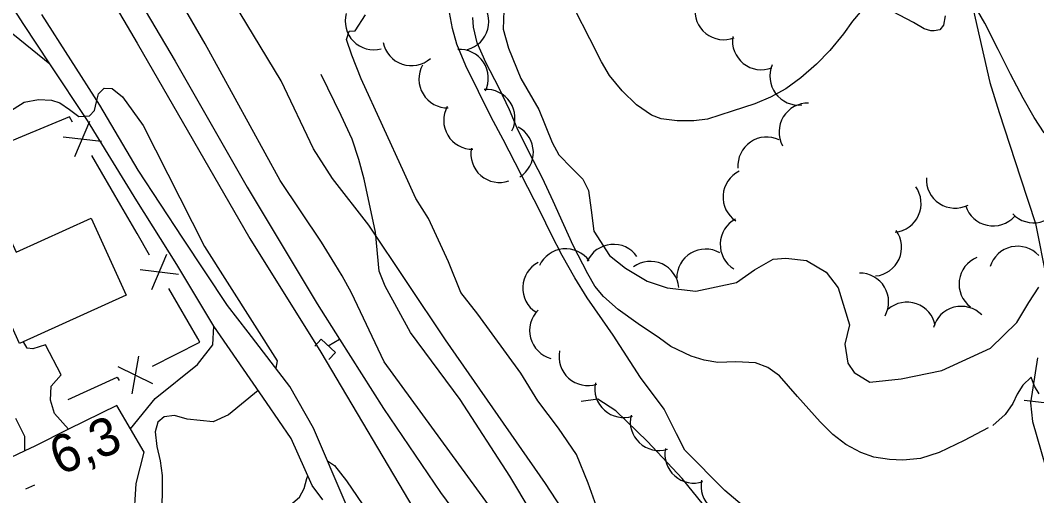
# Model space of a CAD drawing. Extents: x 362852 to 366875, y 5563573 to 5566479.
# Drawn here: x 364339.6 to 364445.4, y 5564921.9 to 5564971.4 of the extents above; entities that cross this region are included whole.
import ezdxf

# ---------------------------------------------------------------- set-up
doc = ezdxf.new("R2010")
doc.units = 0
for name, color, linetype in [('Niveau 1', 7, 'Continuous'), ('Niveau 19', 7, 'Continuous'), ('Niveau 2', 7, 'Continuous'), ('Niveau 21', 7, 'Continuous'), ('Niveau 22', 7, 'Continuous'), ('Niveau 26', 7, 'Continuous'), ('Niveau 3', 7, 'Continuous'), ('Niveau 31', 7, 'Continuous'), ('Niveau 37', 7, 'Continuous'), ('Niveau 4', 7, 'Continuous'), ('Niveau 44', 7, 'Continuous')]:
    doc.layers.add(name, color=color, linetype=linetype)

msp = doc.modelspace()

# ---------------------------------------------------------------- linework, layer by layer
at = {"layer": 'Niveau 1'}
for points in [[(364401.32, 5564938.56), (364400.2, 5564940.18), (364398.62, 5564942.47), (364397.33, 5564944.56), (364396.02, 5564946.86), (364394.86, 5564949.08), (364393.75, 5564951.38), (364392.42, 5564953.96), (364391.12, 5564956.53), (364389.85, 5564958.94), (364388.61, 5564961.29), (364387.3, 5564963.94), (364385.98, 5564966.61), (364385.03, 5564968.88), (364384.58, 5564970.52), (364384.29, 5564972.19), (364384.07, 5564973.39), (364383.72, 5564973.8)], [(364470.03, 5564888.41), (364466.89, 5564889.74), (364464.83, 5564893.08), (364460.41, 5564900.33), (364455.85, 5564906.41), (364452.83, 5564911.75), (364450.44, 5564916.21), (364449.3, 5564917.79), (364448.42, 5564918.36), (364447.47, 5564916.05), (364444.95, 5564913.74), (364439.93, 5564911.44), (364435.17, 5564911.23), (364430.09, 5564912.75), (364425.67, 5564914.79), (364420.35, 5564916.68), (364416.81, 5564919.14), (364412.95, 5564922.4), (364408.78, 5564926.59), (364407.91, 5564928.29), (364406.62, 5564930.86), (364404.17, 5564934.15), (364401.32, 5564938.56)]]:
    msp.add_lwpolyline(points, dxfattribs=at)
at = {"layer": 'Niveau 19'}
for points in [[(364371.09, 5564921.42), (364369.98, 5564922.91), (364367.8, 5564927.81), (364365.23, 5564931.56), (364359.73, 5564939.51), (364355.89, 5564945.92), (364351.73, 5564952.56), (364346.58, 5564960.94), (364342.66, 5564966.84), (364339.96, 5564970.91), (364335.29, 5564978.17)], [(364446.52, 5564826.2), (364439.4, 5564834), (364433.05, 5564842.48), (364429.25, 5564847.71), (364423.9, 5564854.18), (364418.74, 5564859.91), (364412.38, 5564866.59), (364407.73, 5564872.41), (364402.82, 5564877.5), (364399.08, 5564882.94), (364390.62, 5564894.66), (364384.3, 5564903.22), (364378.76, 5564910.47), (364376.94, 5564913.47), (364374.94, 5564917.45), (364373.52, 5564920.93), (364370.11, 5564928.88), (364367.65, 5564933.24), (364363.33, 5564938.88), (364361.15, 5564941.66), (364356.52, 5564948.67), (364351.86, 5564955.74), (364347.86, 5564962.52), (364341.84, 5564971.98)], [(364344.62, 5564928.77), (364343.16, 5564930.41), (364342.73, 5564931.79), (364342.82, 5564933.26), (364343.84, 5564934.43), (364342.21, 5564937.56), (364340.89, 5564937.14), (364340.3, 5564937.21), (364339.94, 5564937.89)], [(364340.06, 5564926.52), (364340.07, 5564928.02), (364339.12, 5564929.88)]]:
    msp.add_lwpolyline(points, dxfattribs=at)
at = {"layer": 'Niveau 2'}
for points in [[(364213.35, 5565146.39), (364232.53, 5565126.45), (364248.39, 5565109.34), (364263.13, 5565093.41), (364276.11, 5565079.71), (364286.64, 5565068.01), (364298.72, 5565050.81), (364312.47, 5565031.31), (364325.73, 5565011.49), (364339.55, 5564989.79), (364351.77, 5564968.99), (364363.49, 5564948.63), (364370.89, 5564936.8), (364381.12, 5564919.52), (364394.15, 5564902.4), (364400.15, 5564894.19), (364412.12, 5564878.44), (364425.03, 5564863.91), (364445.83, 5564836.95)], [(364448.42, 5564846.74), (364439.7, 5564857.82), (364433.96, 5564865.25), (364422.86, 5564878.54), (364417.41, 5564885.85), (364417.07, 5564886.4), (364416.7, 5564888.08), (364410.82, 5564892.76), (364404.29, 5564900.44), (364392.1, 5564915.78), (364377.46, 5564935.81), (364374.07, 5564942.97), (364373.1, 5564944.76), (364372.34, 5564946.01), (364370.94, 5564948.25), (364366.66, 5564954.67), (364358.85, 5564968.9), (364349.12, 5564985.71)], [(364400.99, 5564912.83), (364394.28, 5564923.11), (364383.87, 5564938.1), (364375.87, 5564950.03), (364372.1, 5564954.9), (364370.12, 5564957.96), (364366.75, 5564965.06), (364358.11, 5564979.35)], [(364446.2, 5564959.65), (364445.14, 5564961.23), (364444.02, 5564963.25), (364442.7, 5564965.76), (364441.39, 5564968.33), (364440.02, 5564971.08), (364438.73, 5564973.29)], [(364373.83, 5564970.24), (364374.45, 5564970.25), (364375.52, 5564971.93)], [(364389.95, 5564972.4), (364389.87, 5564970.45), (364390.43, 5564968.45), (364391.7, 5564965.31), (364393.57, 5564962.06), (364394.95, 5564958.65), (364395.66, 5564957.34), (364397.02, 5564955.97), (364398.16, 5564954.83), (364398.76, 5564953.65), (364399.03, 5564951.6), (364399.3, 5564949.41), (364400.94, 5564946.87), (364402.59, 5564945.56), (364404.87, 5564944.2), (364406.94, 5564943.5), (364409.92, 5564943.17), (364414.15, 5564944.04), (364416.02, 5564945.36), (364417.99, 5564946.48), (364419.31, 5564946.58), (364421.44, 5564946.34), (364423.48, 5564945.13), (364424.76, 5564943.49), (364425.94, 5564939.64), (364425.45, 5564937.64), (364425.75, 5564935.66), (364426.4, 5564934.69), (364428.04, 5564933.69), (364431.3, 5564934.03), (364435.53, 5564934.9), (364440.59, 5564937.22), (364443.34, 5564939.89), (364444.61, 5564941.96), (364445.64, 5564943.56)], [(364427.05, 5564972.21), (364426.23, 5564971.27), (364425.29, 5564969.95), (364423.87, 5564968.23), (364422.47, 5564966.8), (364420.84, 5564965.38), (364419.29, 5564964.22), (364417.69, 5564963.35), (364416.05, 5564962.68), (364413.72, 5564961.89), (364411.15, 5564961.06), (364409.73, 5564960.91), (364407.97, 5564960.91), (364406.33, 5564961.11), (364405.3, 5564961.5), (364403.76, 5564962.57), (364402.24, 5564964.03), (364400.94, 5564965.63), (364400.12, 5564967.04), (364398.89, 5564969.42), (364397.31, 5564972.5)], [(364435.89, 5564971.82), (364435.72, 5564970.85), (364435.33, 5564970.38), (364434.75, 5564970.26), (364434.39, 5564970.27), (364433.68, 5564970.46), (364432.57, 5564971.13), (364430.39, 5564972.28)], [(364440.35, 5564928.91), (364437.86, 5564927.61), (364435.25, 5564926.34), (364433.32, 5564925.73), (364431.47, 5564925.54), (364430.09, 5564925.61), (364428.46, 5564925.86), (364427.12, 5564926.35), (364425.55, 5564927.19), (364424.2, 5564928.23), (364422.86, 5564929.55), (364420.5, 5564932.2), (364418.62, 5564934.33), (364417.43, 5564935.19), (364416.14, 5564935.68), (364414.1, 5564935.79), (364412.23, 5564935.71), (364410.8, 5564935.96), (364409.43, 5564936.4), (364407.31, 5564937.4), (364406.15, 5564938.25), (364403.91, 5564939.74), (364401.83, 5564941.25), (364400.31, 5564942.61), (364399.4, 5564943.68), (364398.68, 5564944.95), (364397.16, 5564947.9), (364396.19, 5564950.06), (364395.07, 5564952.51), (364393.96, 5564954.93), (364392.57, 5564957.61), (364391.32, 5564960.12), (364390.51, 5564962.05), (364389.44, 5564964.31), (364388.05, 5564966.98), (364387.16, 5564969.01), (364386.76, 5564970.66), (364386.71, 5564971.67)], [(364436.08, 5564904.15), (364425.61, 5564904.22), (364421.12, 5564905.49), (364410.33, 5564908.53), (364404.44, 5564913.58), (364401.28, 5564917.39), (364399.75, 5564920.25), (364398.7, 5564923.17), (364397.49, 5564926.16), (364395.64, 5564928.89), (364393.49, 5564931.74), (364391.71, 5564934.62), (364387.24, 5564940.76), (364385.46, 5564943.01), (364384.17, 5564946.22), (364382.1, 5564950.72), (364380.76, 5564952.79), (364379.58, 5564955.41), (364375.09, 5564965.28), (364374.1, 5564967.74), (364373.56, 5564969.38), (364373.83, 5564970.24)], [(364336.47, 5564960.63), (364340.01, 5564962.83), (364341.5, 5564963.13), (364342.84, 5564963.06), (364343.7, 5564962.78), (364344.73, 5564962.08), (364345.7, 5564961.36), (364346.8, 5564961.43), (364347.33, 5564961.96), (364347.53, 5564962.86), (364347.75, 5564963.69), (364348.31, 5564964.3), (364349.14, 5564964.26), (364350.23, 5564963.4), (364352.38, 5564960.41), (364358.77, 5564947.82), (364366.33, 5564935.9), (364366.19, 5564935.14)], [(364445.67, 5564932.47), (364445.2, 5564933.25), (364444.85, 5564934.2), (364443.98, 5564933.35), (364443.39, 5564932.42), (364442.93, 5564931.44), (364442.12, 5564930.32), (364440.86, 5564929.17), (364440.86, 5564929.17)], [(364364.36, 5564932.81), (364361.26, 5564930.27), (364359.68, 5564929.56), (364356.96, 5564929.82), (364355.63, 5564930.21), (364354.56, 5564930.08), (364353.92, 5564929.51), (364353.63, 5564928.52)], [(364353.63, 5564928.52), (364353.82, 5564926.97), (364354.17, 5564925.5), (364354.36, 5564923.95), (364354.37, 5564922.09), (364354.29, 5564920.12), (364354.69, 5564919.29), (364355.25, 5564918.83), (364356.02, 5564918.78), (364361.41, 5564920.05), (364362.87, 5564920.15), (364364.59, 5564919.73), (364366.04, 5564919.7), (364366.76, 5564920.06), (364368.65, 5564921.71), (364369.16, 5564922.6), (364369.42, 5564923.64), (364369.53, 5564923.91)], [(364371.57, 5564925.48), (364372.29, 5564925.01), (364373.56, 5564923.41), (364380.2, 5564913.6)]]:
    msp.add_lwpolyline(points, dxfattribs=at)
at = {"layer": 'Niveau 21'}
msp.add_lwpolyline([(364351.41, 5564919.16), (364351.67, 5564923.13), (364352.48, 5564926.38), (364351.06, 5564928.82), (364349.63, 5564931.26), (364344.62, 5564928.77), (364341.09, 5564927.01), (364340.06, 5564926.52), (364332.68, 5564923.01)], dxfattribs=at)
at = {"layer": 'Niveau 22'}
for points in [[(364283.63, 5564977.26), (364284.39, 5564977.32), (364288.99, 5564976.58), (364295.38, 5564974.16), (364297.32, 5564973.83), (364308.97, 5564973.93), (364311.65, 5564974.05), (364323.03, 5564975.27), (364328.84, 5564975.22), (364334.63, 5564973.53), (364338.26, 5564970.4), (364342.66, 5564966.84)], [(364429.52, 5564888.29), (364426.62, 5564889.6), (364423.64, 5564890.31), (364421.59, 5564890.59), (364418.46, 5564891.24), (364411.65, 5564896.06), (364407.06, 5564900.66), (364401.12, 5564907.83), (364397.17, 5564913.63), (364392.78, 5564920.19), (364390.55, 5564923.88), (364385.4, 5564931.87), (364380.21, 5564938.85), (364377.57, 5564943.69), (364376.94, 5564945.24), (364376.59, 5564949.3), (364375.41, 5564954.82), (364374.84, 5564956.88), (364374.13, 5564958.99), (364373, 5564961.46), (364370.91, 5564965.72)], [(364351.06, 5564928.82), (364353.63, 5564931.97), (364358.05, 5564935.52), (364359.64, 5564937.55), (364359.73, 5564939.51)], [(364467.05, 5564835.61), (364465.22, 5564839.99), (364462.54, 5564844.92), (364460.37, 5564847.83), (364457.75, 5564851.27), (364449.32, 5564860.89), (364440.88, 5564870.83), (364434.81, 5564878.93), (364432.3, 5564883.14), (364431, 5564886.03), (364429.52, 5564888.29), (364427.47, 5564893.81), (364426.66, 5564896.15), (364425.81, 5564898.43), (364423.38, 5564902.03), (364419.66, 5564908.15), (364417.83, 5564911.68), (364414, 5564916.88), (364408.49, 5564923.63), (364404.88, 5564927.49), (364401.58, 5564930.69), (364399.71, 5564931.92), (364398, 5564931.67)], [(364465.05, 5564922.84), (364461.03, 5564924.97), (364457.35, 5564927.06), (364453.26, 5564930.15), (364451.21, 5564930.92), (364444.12, 5564931.76)]]:
    msp.add_lwpolyline(points, dxfattribs=at)
at = {"layer": 'Niveau 26'}
for p, q in [((364370.92, 5564938.15), (364370.25, 5564937.42)), ((364370.92, 5564938.15), (364372.4, 5564936.78)), ((364372.4, 5564936.78), (364371.71, 5564936.05))]:
    msp.add_line(p, q, dxfattribs=at)
at = {"layer": 'Niveau 3'}
msp.add_line((364340.16, 5564922.58), (364341.12, 5564922.97), dxfattribs=at)
at = {"layer": 'Niveau 31'}
msp.add_lwpolyline([(364350.62, 5564942.74), (364339.51, 5564937.69), (364335.31, 5564946.93), (364338.61, 5564948.43), (364339.15, 5564947.22), (364346.97, 5564950.77), (364350.62, 5564942.74)], dxfattribs=at)
at = {"layer": 'Niveau 37'}
for p, q in [((364345.27, 5564957.17), (364346.84, 5564960.85)), ((364339.78, 5564959.25), (364334.24, 5564956.95)), ((364344.07, 5564959.24), (364348.04, 5564958.77)), ((364350.06, 5564952.09), (364347.05, 5564957.28)), ((364353.28, 5564943.32), (364354.86, 5564947)), ((364352.08, 5564945.4), (364356.06, 5564944.92)), ((364358.07, 5564938.24), (364355.07, 5564943.43)), ((364351.9, 5564936.4), (364351.21, 5564932.46)), ((364349.76, 5564935.31), (364353.35, 5564933.54))]:
    msp.add_line(p, q, dxfattribs=at)
for points in [[(364345.04, 5564960.74), (364344.72, 5564961.3), (364339.78, 5564959.25)], [(364353.06, 5564946.9), (364351.75, 5564949.17), (364350.06, 5564952.09)], [(364353.34, 5564935.34), (364358.29, 5564937.85), (364358.07, 5564938.24)], [(364344.59, 5564931.88), (364349.68, 5564934.21), (364349.87, 5564933.86)]]:
    msp.add_lwpolyline(points, dxfattribs=at)
at = {"layer": 'Niveau 4'}
msp.add_line((364371.65, 5564937.47), (364372.82, 5564938.16), dxfattribs=at)
for points in [[(364348.46, 5564979.38), (364355.72, 5564967.11), (364363.21, 5564953.99), (364370.49, 5564941.85), (364372.82, 5564938.16), (364377.39, 5564930.93), (364383.35, 5564922.2), (364389.82, 5564913.42), (364399.6, 5564901.43), (364409.09, 5564888.9), (364410.82, 5564886.77), (364419.66, 5564875.87), (364429.16, 5564864.4), (364438.6, 5564853.22), (364446.64, 5564841.78)], [(364438.82, 5564972.36), (364440.54, 5564964.88), (364441.49, 5564961.76), (364443.74, 5564954.95), (364445.29, 5564950.21), (364446.44, 5564944.44)], [(364445.48, 5564936.22), (364444.76, 5564931.54), (364444.99, 5564929.59), (364446.33, 5564924.88)]]:
    msp.add_lwpolyline(points, dxfattribs=at)
at = {"layer": 'Niveau 44'}
for centre, start, end in [((364385.37, 5564971.21), 285.2152, 45.1932), ((364412.84, 5564972.34), 171.258, 291.2359), ((364376.41, 5564971.29), 164.6496, 284.6276), ((364416.74, 5564969.21), 171.258, 291.2359), ((364380.31, 5564969.64), 191.1842, 311.1621), ((364385.32, 5564965.33), 333.6957, 93.6736), ((364384.1, 5564965.23), 150.8925, 270.8705), ((364420.63, 5564965.53), 156.3744, 276.3524), ((364388.09, 5564961.17), 333.6957, 93.6736), ((364386.67, 5564960.93), 150.8925, 270.8705), ((364421.59, 5564959.74), 88.6219, 208.5998), ((364390.01, 5564957.6), 301.6714, 61.6493), ((364417.3, 5564956.21), 64.5163, 184.4942), ((364389.5, 5564957.47), 168.8354, 288.8134), ((364415.75, 5564952.95), 116.0397, 236.0176), ((364436.92, 5564954.8), 176.8774, 296.8554), ((364430.38, 5564952.28), 275.8478, 35.8257), ((364440.87, 5564952.95), 198.0716, 318.0495), ((364445.09, 5564953.27), 223.47, 343.4479), ((364415.46, 5564948.02), 118.1663, 238.1442), ((364428.34, 5564947.72), 275.8478, 35.8257), ((364396.37, 5564944.57), 35.3062, 155.2841), ((364401.35, 5564945.03), 35.3062, 155.2841), ((364410.94, 5564944.54), 60.6336, 180.6115), ((364443.43, 5564944.83), 42.8963, 162.8743), ((364440.33, 5564943.89), 112.6603, 232.6382), ((364394.9, 5564943.49), 117.5816, 237.5596), ((364405.18, 5564943.25), 5.7851, 125.7631), ((364427, 5564942.04), 330.9463, 90.9242), ((364395.62, 5564939.05), 134.883, 254.861), ((364431.91, 5564939.01), 10.9957, 130.9737), ((364437.55, 5564938.57), 44.513, 164.4909), ((364398.68, 5564936.32), 168.2173, 288.1952), ((364402.4, 5564932.99), 168.2173, 288.1952), ((364406.1, 5564929.56), 166.6751, 286.653), ((364409.7, 5564926.17), 168.7738, 288.7517), ((364413.46, 5564922.88), 168.7738, 288.7517)]:
    msp.add_arc(centre, 3, start, end, dxfattribs=at)

# ---------------------------------------------------------------- texts
at = {"layer": 'Niveau 3'}
msp.add_text('6,3  ', height=3.93, rotation=22.09, dxfattribs=at).set_placement((364343.67, 5564923.94))

doc.saveas('drawing.dxf')
